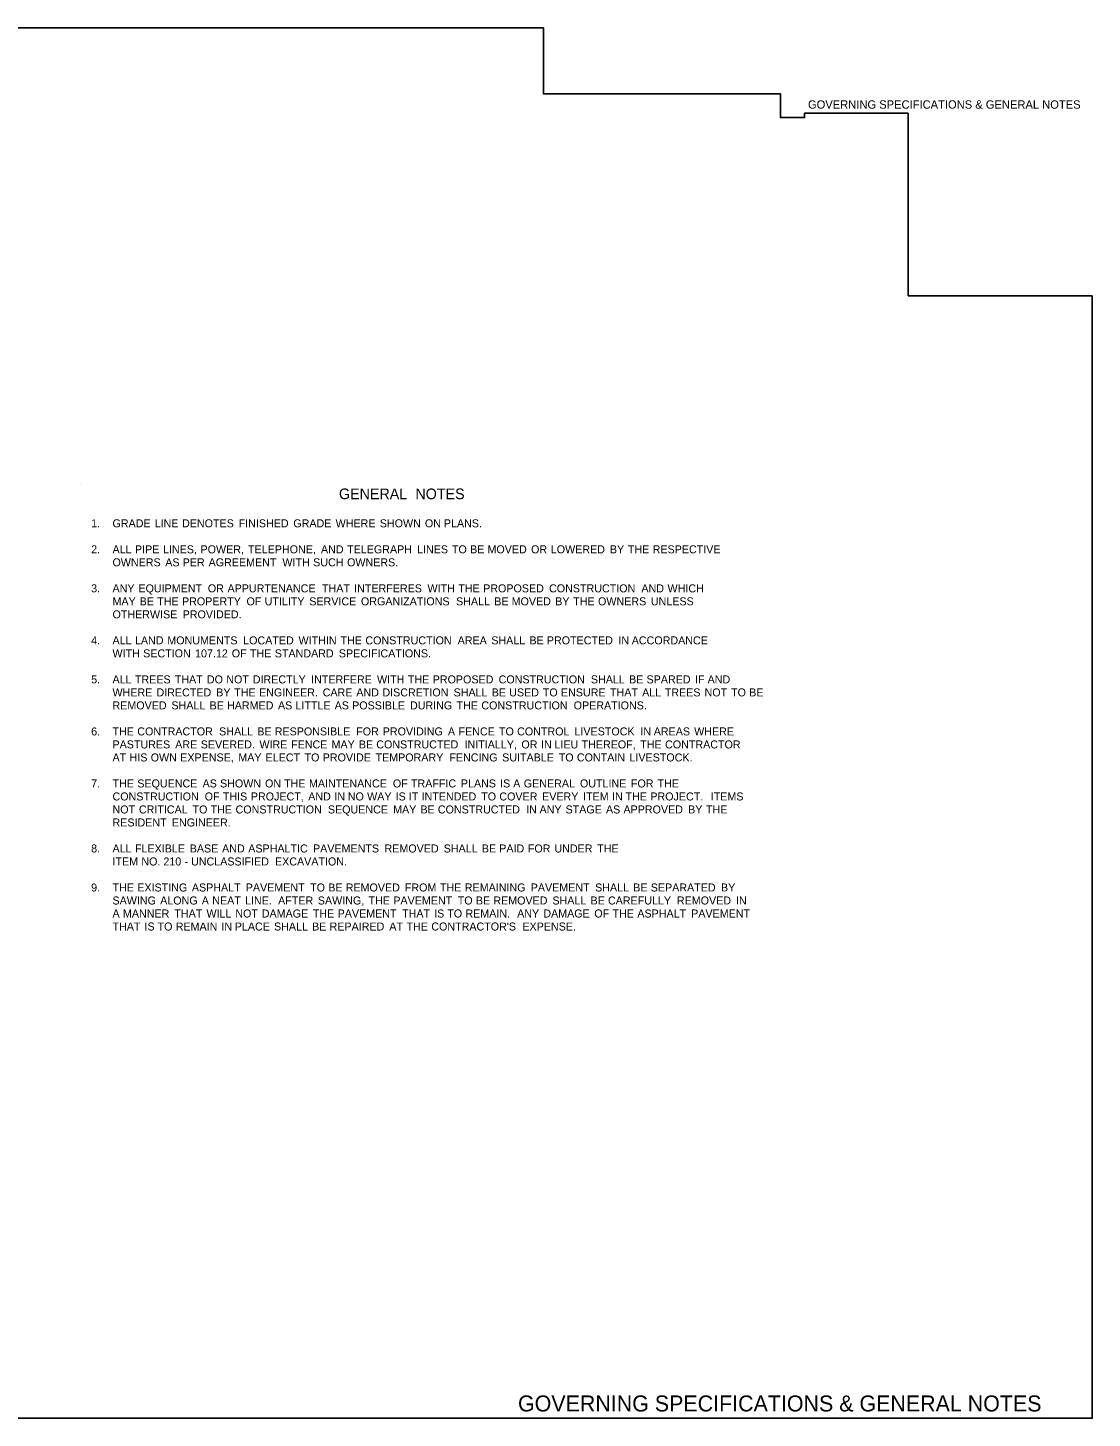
# Model space of a CAD drawing. Extents: x 1955683 to 1956002, y 566394 to 566602.
# Drawn here: x 1955842.9 to 1956002.5, y 566393.5 to 566602 of the extents above; entities that cross this region are included whole.
import ezdxf

# ---------------------------------------------------------------- set-up
doc = ezdxf.new("R2010")
doc.units = 0
for name, color, linetype in [('Default', 7, 'Continuous'), ('R_Border', 7, 'Continuous'), ('R_Border Prem', 7, 'Continuous'), ('STAMP', 7, 'Continuous')]:
    doc.layers.add(name, color=color, linetype=linetype)

msp = doc.modelspace()

# ---------------------------------------------------------------- linework, layer by layer
at = {"layer": 'Default'}
msp.add_line((1955850.81, 566533.47), (1955850.81, 566533.47), dxfattribs=at)
at = {"layer": 'R_Border Prem'}
for points in [[(1956002.45, 566561.79), (1956002.45, 566393.51), (1955683.38, 566393.51), (1955683.38, 566601.97), (1955920.19, 566601.97), (1955920.19, 566592.09), (1955955.71, 566592.09), (1955955.71, 566588.52), (1955959.35, 566588.52), (1955959.35, 566589.17), (1955974.89, 566589.17)], [(1955974.89, 566589.17), (1955974.89, 566561.79), (1956002.45, 566561.79)]]:
    msp.add_lwpolyline(points, dxfattribs=at)

# ---------------------------------------------------------------- texts
at = {"layer": 'Default'}
for s, height, p in [('GENERAL', 1.6, (1955889.56, 566531.3)), (' NOTES', 1.6, (1955900.42, 566531.3)), ('1.', 1.2, (1955852.41, 566527.08)), ('GRADE', 1.2, (1955855.61, 566527.08)), (' LINE', 1.2, (1955861.48, 566527.08)), (' DENOTES', 1.2, (1955865.59, 566527.08)), (' FINISHED', 1.2, (1955874.07, 566527.08)), (' GRADE', 1.2, (1955882.27, 566527.08)), (' WHERE', 1.2, (1955888.61, 566527.08)), (' SHOWN', 1.2, (1955895.23, 566527.08)), (' ON', 1.2, (1955901.99, 566527.08)), (' PLANS.', 1.2, (1955904.83, 566527.08)), ('2.', 1.2, (1955852.41, 566523.18)), ('ALL', 1.2, (1955855.61, 566523.18)), (' PIPE', 1.2, (1955858.53, 566523.18)), (' LINES,', 1.2, (1955862.73, 566523.18)), (' POWER,', 1.2, (1955868.36, 566523.18)), (' TELEPHONE,', 1.2, (1955875.48, 566523.18)), (' AND', 1.2, (1955886.41, 566523.18)), (' TELEGRAPH', 1.2, (1955890.33, 566523.18)), (' LINES', 1.2, (1955900.82, 566523.18)), (' TO', 1.2, (1955906.04, 566523.18)), (' BE', 1.2, (1955908.76, 566523.18)), (' MOVED', 1.2, (1955911.37, 566523.18)), (' OR', 1.2, (1955917.9, 566523.18)), (' LOWERED', 1.2, (1955920.86, 566523.18)), (' BY', 1.2, (1955929.71, 566523.18)), (' THE', 1.2, (1955932.4, 566523.18)), (' RESPECTIVE', 1.2, (1955936.13, 566523.18)), ('OWNERS', 1.2, (1955855.61, 566521.23)), (' AS', 1.2, (1955863.07, 566521.23)), (' PER', 1.2, (1955865.68, 566521.23)), (' AGREEMENT', 1.2, (1955869.57, 566521.23)), (' WITH', 1.2, (1955880.63, 566521.23)), (' SUCH', 1.2, (1955885.24, 566521.23)), (' OWNERS.', 1.2, (1955890.32, 566521.23)), ('3.', 1.2, (1955852.41, 566517.33)), ('ANY', 1.2, (1955855.61, 566517.33)), ('MAY', 1.2, (1955855.61, 566515.38)), (' EQUIPMENT', 1.2, (1955859.05, 566517.33)), (' BE', 1.2, (1955859.23, 566515.38)), (' THE', 1.2, (1955861.85, 566515.38)), (' PROPERTY', 1.2, (1955865.58, 566515.38)), (' OR', 1.2, (1955869.45, 566517.33)), (' APPURTENANCE', 1.2, (1955872.4, 566517.33)), (' OF', 1.2, (1955875.25, 566515.38)), (' UTILITY', 1.2, (1955877.97, 566515.38)), (' SERVICE', 1.2, (1955884.66, 566515.38)), (' THAT', 1.2, (1955886.57, 566517.33)), (' INTERFERES', 1.2, (1955891.38, 566517.33)), (' ORGANIZATIONS', 1.2, (1955892.4, 566515.38)), (' WITH', 1.2, (1955902.38, 566517.33)), (' SHALL', 1.2, (1955906.66, 566515.38)), (' THE', 1.2, (1955906.99, 566517.33)), (' PROPOSED', 1.2, (1955910.72, 566517.33)), (' BE', 1.2, (1955912.38, 566515.38)), (' MOVED', 1.2, (1955914.99, 566515.38)), (' CONSTRUCTION', 1.2, (1955920.6, 566517.33)), (' BY', 1.2, (1955921.52, 566515.38)), (' THE', 1.2, (1955924.21, 566515.38)), (' OWNERS', 1.2, (1955927.94, 566515.38)), (' AND', 1.2, (1955934.44, 566517.33)), (' UNLESS', 1.2, (1955935.86, 566515.38)), (' WHICH', 1.2, (1955938.36, 566517.33)), ('OTHERWISE', 1.2, (1955855.61, 566513.43)), (' PROVIDED.', 1.2, (1955865.68, 566513.43)), ('4.', 1.2, (1955852.41, 566509.53)), ('ALL', 1.2, (1955855.61, 566509.53)), (' LAND', 1.2, (1955858.53, 566509.53)), (' MONUMENTS', 1.2, (1955863.38, 566509.53)), (' LOCATED', 1.2, (1955874.75, 566509.53)), (' WITHIN', 1.2, (1955883.05, 566509.53)), (' THE', 1.2, (1955889.34, 566509.53)), (' CONSTRUCTION', 1.2, (1955893.07, 566509.53)), (' AREA', 1.2, (1955906.9, 566509.53)), (' SHALL', 1.2, (1955911.94, 566509.53)), (' BE', 1.2, (1955917.66, 566509.53)), (' PROTECTED', 1.2, (1955920.27, 566509.53)), (' IN', 1.2, (1955930.99, 566509.53)), (' ACCORDANCE', 1.2, (1955932.99, 566509.53)), ('WITH', 1.2, (1955855.61, 566507.58)), (' SECTION', 1.2, (1955859.76, 566507.58)), (' 107.12', 1.2, (1955867.54, 566507.58)), (' OF', 1.2, (1955873.04, 566507.58)), (' THE', 1.2, (1955875.76, 566507.58)), (' STANDARD', 1.2, (1955879.49, 566507.58)), (' SPECIFICATIONS.', 1.2, (1955889.09, 566507.58)), ('5.', 1.2, (1955852.41, 566503.68)), ('ALL', 1.2, (1955855.61, 566503.68)), (' TREES', 1.2, (1955858.53, 566503.68)), (' THAT', 1.2, (1955864.5, 566503.68)), (' DO', 1.2, (1955869.31, 566503.68)), (' NOT', 1.2, (1955872.22, 566503.68)), (' DIRECTLY', 1.2, (1955876.19, 566503.68)), (' INTERFERE', 1.2, (1955884.94, 566503.68)), (' WITH', 1.2, (1955894.81, 566503.68)), (' THE', 1.2, (1955899.43, 566503.68)), (' PROPOSED', 1.2, (1955903.16, 566503.68)), (' CONSTRUCTION', 1.2, (1955913.04, 566503.68)), (' SHALL', 1.2, (1955926.87, 566503.68)), (' BE', 1.2, (1955932.59, 566503.68)), (' SPARED', 1.2, (1955935.21, 566503.68)), (' IF', 1.2, (1955942.48, 566503.68)), (' AND', 1.2, (1955944.36, 566503.68)), ('WHERE', 1.2, (1955855.61, 566501.73)), (' DIRECTED', 1.2, (1955861.76, 566501.73)), (' BY', 1.2, (1955870.71, 566501.73)), (' THE', 1.2, (1955873.4, 566501.73)), (' ENGINEER.', 1.2, (1955877.13, 566501.73)), (' CARE', 1.2, (1955886.67, 566501.73)), (' AND', 1.2, (1955891.71, 566501.73)), (' DISCRETION', 1.2, (1955895.62, 566501.73)), (' SHALL', 1.2, (1955906.29, 566501.73)), (' BE', 1.2, (1955912.01, 566501.73)), (' USED', 1.2, (1955914.63, 566501.73)), (' TO', 1.2, (1955919.66, 566501.73)), (' ENSURE', 1.2, (1955922.38, 566501.73)), (' THAT', 1.2, (1955929.74, 566501.73)), (' ALL', 1.2, (1955934.55, 566501.73)), (' TREES', 1.2, (1955937.94, 566501.73)), (' NOT', 1.2, (1955943.91, 566501.73)), (' TO', 1.2, (1955947.88, 566501.73)), (' BE', 1.2, (1955950.6, 566501.73)), ('REMOVED', 1.2, (1955855.61, 566499.78)), (' SHALL', 1.2, (1955864, 566499.78)), (' BE', 1.2, (1955869.72, 566499.78)), (' HARMED', 1.2, (1955872.33, 566499.78)), (' AS', 1.2, (1955879.97, 566499.78)), (' LITTLE', 1.2, (1955882.59, 566499.78)), (' AS', 1.2, (1955888.46, 566499.78)), (' POSSIBLE', 1.2, (1955891.08, 566499.78)), (' DURING', 1.2, (1955899.75, 566499.78)), (' THE', 1.2, (1955906.72, 566499.78)), (' CONSTRUCTION', 1.2, (1955910.45, 566499.78)), (' OPERATIONS.', 1.2, (1955924.29, 566499.78)), ('6.', 1.2, (1955852.41, 566495.88)), ('THE', 1.2, (1955855.61, 566495.88)), (' CONTRACTOR', 1.2, (1955858.88, 566495.88)), (' SHALL', 1.2, (1955871.15, 566495.88)), (' BE', 1.2, (1955876.87, 566495.88)), (' RESPONSIBLE', 1.2, (1955879.48, 566495.88)), (' FOR', 1.2, (1955891.69, 566495.88)), (' PROVIDING', 1.2, (1955895.67, 566495.88)), (' A', 1.2, (1955905.44, 566495.88)), (' FENCE', 1.2, (1955907.03, 566495.88)), (' TO', 1.2, (1955913.09, 566495.88)), (' CONTROL', 1.2, (1955915.81, 566495.88)), (' LIVESTOCK', 1.2, (1955924.41, 566495.88)), (' IN', 1.2, (1955934.29, 566495.88)), (' AREAS', 1.2, (1955936.29, 566495.88)), (' WHERE', 1.2, (1955942.35, 566495.88)), ('PASTURES', 1.2, (1955855.61, 566493.93)), (' ARE', 1.2, (1955864.56, 566493.93)), (' SEVERED.', 1.2, (1955868.39, 566493.93)), (' WIRE', 1.2, (1955877.19, 566493.93)), (' FENCE', 1.2, (1955881.94, 566493.93)), (' MAY', 1.2, (1955888, 566493.93)), (' BE', 1.2, (1955892.09, 566493.93)), (' CONSTRUCTED', 1.2, (1955894.7, 566493.93)), (' INITIALLY,', 1.2, (1955907.93, 566493.93)), (' OR', 1.2, (1955916.45, 566493.93)), (' IN', 1.2, (1955919.4, 566493.93)), (' LIEU', 1.2, (1955921.41, 566493.93)), (' THEREOF,', 1.2, (1955925.47, 566493.93)), (' THE', 1.2, (1955934.26, 566493.93)), (' CONTRACTOR', 1.2, (1955937.99, 566493.93)), ('AT', 1.2, (1955855.61, 566491.98)), (' HIS', 1.2, (1955857.72, 566491.98)), (' OWN', 1.2, (1955860.89, 566491.98)), (' EXPENSE,', 1.2, (1955865.32, 566491.98)), (' MAY', 1.2, (1955874.02, 566491.98)), (' ELECT', 1.2, (1955878.11, 566491.98)), (' TO', 1.2, (1955883.95, 566491.98)), (' PROVIDE', 1.2, (1955886.67, 566491.98)), (' TEMPORARY', 1.2, (1955894.59, 566491.98)), (' FENCING', 1.2, (1955905.66, 566491.98)), (' SUITABLE', 1.2, (1955913.57, 566491.98)), (' TO', 1.2, (1955922.05, 566491.98)), (' CONTAIN', 1.2, (1955924.77, 566491.98)), (' LIVESTOCK.', 1.2, (1955932.65, 566491.98)), ('7.', 1.2, (1955852.41, 566488.08)), ('THE', 1.2, (1955855.61, 566488.08)), ('CONSTRUCTION', 1.2, (1955855.61, 566486.13)), (' SEQUENCE', 1.2, (1955858.88, 566488.08)), (' AS', 1.2, (1955868.66, 566488.08)), (' OF', 1.2, (1955868.98, 566486.13)), (' SHOWN', 1.2, (1955871.28, 566488.08)), (' THIS', 1.2, (1955871.7, 566486.13)), (' PROJECT,', 1.2, (1955875.9, 566486.13)), (' ON', 1.2, (1955878.03, 566488.08)), (' THE', 1.2, (1955880.88, 566488.08)), (' AND', 1.2, (1955884.5, 566486.13)), (' MAINTENANCE', 1.2, (1955884.61, 566488.08)), (' IN', 1.2, (1955888.42, 566486.13)), (' NO', 1.2, (1955890.43, 566486.13)), (' WAY', 1.2, (1955893.33, 566486.13)), (' OF', 1.2, (1955897.19, 566488.08)), (' IS', 1.2, (1955897.6, 566486.13)), (' IT', 1.2, (1955899.57, 566486.13)), (' TRAFFIC', 1.2, (1955899.9, 566488.08)), (' INTENDED', 1.2, (1955901.49, 566486.13)), (' PLANS', 1.2, (1955907.38, 566488.08)), (' TO', 1.2, (1955910.43, 566486.13)), (' COVER', 1.2, (1955913.15, 566486.13)), (' IS', 1.2, (1955913.26, 566488.08)), (' A', 1.2, (1955915.22, 566488.08)), (' GENERAL', 1.2, (1955916.81, 566488.08)), (' EVERY', 1.2, (1955919.56, 566486.13)), (' OUTLINE', 1.2, (1955925.23, 566488.08)), (' ITEM', 1.2, (1955925.7, 566486.13)), (' IN', 1.2, (1955930.04, 566486.13)), (' THE', 1.2, (1955932.05, 566486.13)), (' FOR', 1.2, (1955932.87, 566488.08)), (' PROJECT.', 1.2, (1955935.78, 566486.13)), (' THE', 1.2, (1955936.85, 566488.08)), ('  ITEMS', 1.2, (1955944.39, 566486.13)), ('NOT', 1.2, (1955855.61, 566484.18)), (' CRITICAL', 1.2, (1955859.12, 566484.18)), (' TO', 1.2, (1955867.16, 566484.18)), (' THE', 1.2, (1955869.88, 566484.18)), (' CONSTRUCTION', 1.2, (1955873.61, 566484.18)), (' SEQUENCE', 1.2, (1955887.45, 566484.18)), (' MAY', 1.2, (1955897.23, 566484.18)), (' BE', 1.2, (1955901.32, 566484.18)), (' CONSTRUCTED', 1.2, (1955903.93, 566484.18)), (' IN', 1.2, (1955917.17, 566484.18)), (' ANY', 1.2, (1955919.17, 566484.18)), (' STAGE', 1.2, (1955923.07, 566484.18)), (' AS', 1.2, (1955929.13, 566484.18)), (' APPROVED', 1.2, (1955931.75, 566484.18)), (' BY', 1.2, (1955941.44, 566484.18)), (' THE', 1.2, (1955944.13, 566484.18)), ('RESIDENT', 1.2, (1955855.61, 566482.23)), (' ENGINEER.', 1.2, (1955864.06, 566482.23)), ('8.', 1.2, (1955852.41, 566478.33)), ('ALL', 1.2, (1955855.61, 566478.33)), (' FLEXIBLE', 1.2, (1955858.53, 566478.33)), (' BASE', 1.2, (1955866.74, 566478.33)), (' AND', 1.2, (1955871.59, 566478.33)), (' ASPHALTIC', 1.2, (1955875.51, 566478.33)), (' PAVEMENTS', 1.2, (1955885.22, 566478.33)), (' REMOVED', 1.2, (1955895.94, 566478.33)), (' SHALL', 1.2, (1955904.8, 566478.33)), (' BE', 1.2, (1955910.52, 566478.33)), (' PAID', 1.2, (1955913.13, 566478.33)), (' FOR', 1.2, (1955917.42, 566478.33)), (' UNDER', 1.2, (1955921.4, 566478.33)), (' THE', 1.2, (1955927.81, 566478.33)), ('ITEM', 1.2, (1955855.61, 566476.38)), (' NO.', 1.2, (1955859.49, 566476.38)), (' 210', 1.2, (1955862.79, 566476.38)), (' -', 1.2, (1955865.97, 566476.38)), (' UNCLASSIFIED', 1.2, (1955866.94, 566476.38)), (' EXCAVATION.', 1.2, (1955879.52, 566476.38)), ('9.', 1.2, (1955852.41, 566472.48)), ('THE', 1.2, (1955855.61, 566472.48)), (' EXISTING', 1.2, (1955858.88, 566472.48)), (' ASPHALT', 1.2, (1955867.06, 566472.48)), (' PAVEMENT', 1.2, (1955875.14, 566472.48)), (' TO', 1.2, (1955884.79, 566472.48)), (' BE', 1.2, (1955887.51, 566472.48)), (' REMOVED', 1.2, (1955890.12, 566472.48)), (' FROM', 1.2, (1955898.98, 566472.48)), (' THE', 1.2, (1955904.25, 566472.48)), (' REMAINING', 1.2, (1955907.98, 566472.48)), (' PAVEMENT', 1.2, (1955917.85, 566472.48)), (' SHALL', 1.2, (1955927.5, 566472.48)), (' BE', 1.2, (1955933.22, 566472.48)), (' SEPARATED', 1.2, (1955935.84, 566472.48)), (' BY', 1.2, (1955946.37, 566472.48)), ('SAWING', 1.2, (1955855.61, 566470.53)), (' ALONG', 1.2, (1955862.31, 566470.53)), (' A', 1.2, (1955868.54, 566470.53)), (' NEAT', 1.2, (1955870.12, 566470.53)), (' LINE.', 1.2, (1955875.03, 566470.53)), ('  AFTER', 1.2, (1955879.54, 566470.53)), (' SAWING,', 1.2, (1955885.94, 566470.53)), (' THE', 1.2, (1955893.53, 566470.53)), (' PAVEMENT', 1.2, (1955897.26, 566470.53)), (' TO', 1.2, (1955906.91, 566470.53)), (' BE', 1.2, (1955909.63, 566470.53)), (' REMOVED', 1.2, (1955912.25, 566470.53)), (' SHALL', 1.2, (1955921.1, 566470.53)), (' BE', 1.2, (1955926.82, 566470.53)), (' CAREFULLY', 1.2, (1955929.43, 566470.53)), (' REMOVED', 1.2, (1955939.76, 566470.53)), (' IN', 1.2, (1955948.62, 566470.53)), ('A', 1.2, (1955855.61, 566468.58)), (' MANNER', 1.2, (1955856.73, 566468.58)), (' THAT', 1.2, (1955864.44, 566468.58)), (' WILL', 1.2, (1955869.25, 566468.58)), (' NOT', 1.2, (1955873.57, 566468.58)), (' DAMAGE', 1.2, (1955877.54, 566468.58)), (' THE', 1.2, (1955885.18, 566468.58)), (' PAVEMENT', 1.2, (1955888.91, 566468.58)), (' THAT', 1.2, (1955898.57, 566468.58)), (' IS', 1.2, (1955903.38, 566468.58)), (' TO', 1.2, (1955905.34, 566468.58)), (' REMAIN.', 1.2, (1955908.06, 566468.58)), ('  ANY', 1.2, (1955915.37, 566468.58)), (' DAMAGE', 1.2, (1955919.74, 566468.58)), (' OF', 1.2, (1955927.38, 566468.58)), (' THE', 1.2, (1955930.1, 566468.58)), (' ASPHALT', 1.2, (1955933.83, 566468.58)), (' PAVEMENT', 1.2, (1955941.9, 566468.58)), ('THAT', 1.2, (1955855.61, 566466.63)), (' IS', 1.2, (1955859.96, 566466.63)), (' TO', 1.2, (1955861.92, 566466.63)), (' REMAIN', 1.2, (1955864.64, 566466.63)), (' IN', 1.2, (1955871.49, 566466.63)), (' PLACE', 1.2, (1955873.49, 566466.63)), (' SHALL', 1.2, (1955879.37, 566466.63)), (' BE', 1.2, (1955885.08, 566466.63)), (' REPAIRED', 1.2, (1955887.7, 566466.63)), (' AT', 1.2, (1955896.65, 566466.63)), (' THE', 1.2, (1955899.22, 566466.63)), (" CONTRACTOR'S", 1.2, (1955902.95, 566466.63)), (' EXPENSE.', 1.2, (1955916.6, 566466.63))]:
    msp.add_text(s, height=height, dxfattribs=at).set_placement(p)
at = {"layer": 'R_Border'}
msp.add_text('GOVERNING SPECIFICATIONS & GENERAL NOTES', height=2.4, rotation=0, dxfattribs=at).set_placement((1955916.39, 566394.52))
at = {"layer": 'STAMP'}
msp.add_text('GOVERNING SPECIFICATIONS & GENERAL NOTES', height=1.25, rotation=360, dxfattribs=at).set_placement((1955959.85, 566589.85))

doc.saveas('drawing.dxf')
